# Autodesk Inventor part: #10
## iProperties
Author: Charles Bliss
Shininess: 64.0
Angle Display Precision: 2
Document Length Units: 11272
Document Angle Units: 11286
Document Time Units: 11279
Document Mass Units: 11290
Document Length Units Precision: 3
Document Angle Units Precision: 2
Compacted: True
PropertySet Name: _Private Model Information
Created: 2002-05
Part Number: #10
Material: Stainless Steel, 410
Description: External Tooth Lock Washer, 410SS, #10
Document SubType Name: Modeling
Designer: Charles Bliss
Control State: 0
Master: False
Checked Out: False
PropertySet Name: Design Tracking Control
Density: 0.0
Volumn: 0.0
Area: 0.0
PropertySet Name: Model Information
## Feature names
1. Extrusion2
2. Loft1
3. FillID [Extrusion]
4. Circular Pattern1
5. FillPat [Circular Pattern]
